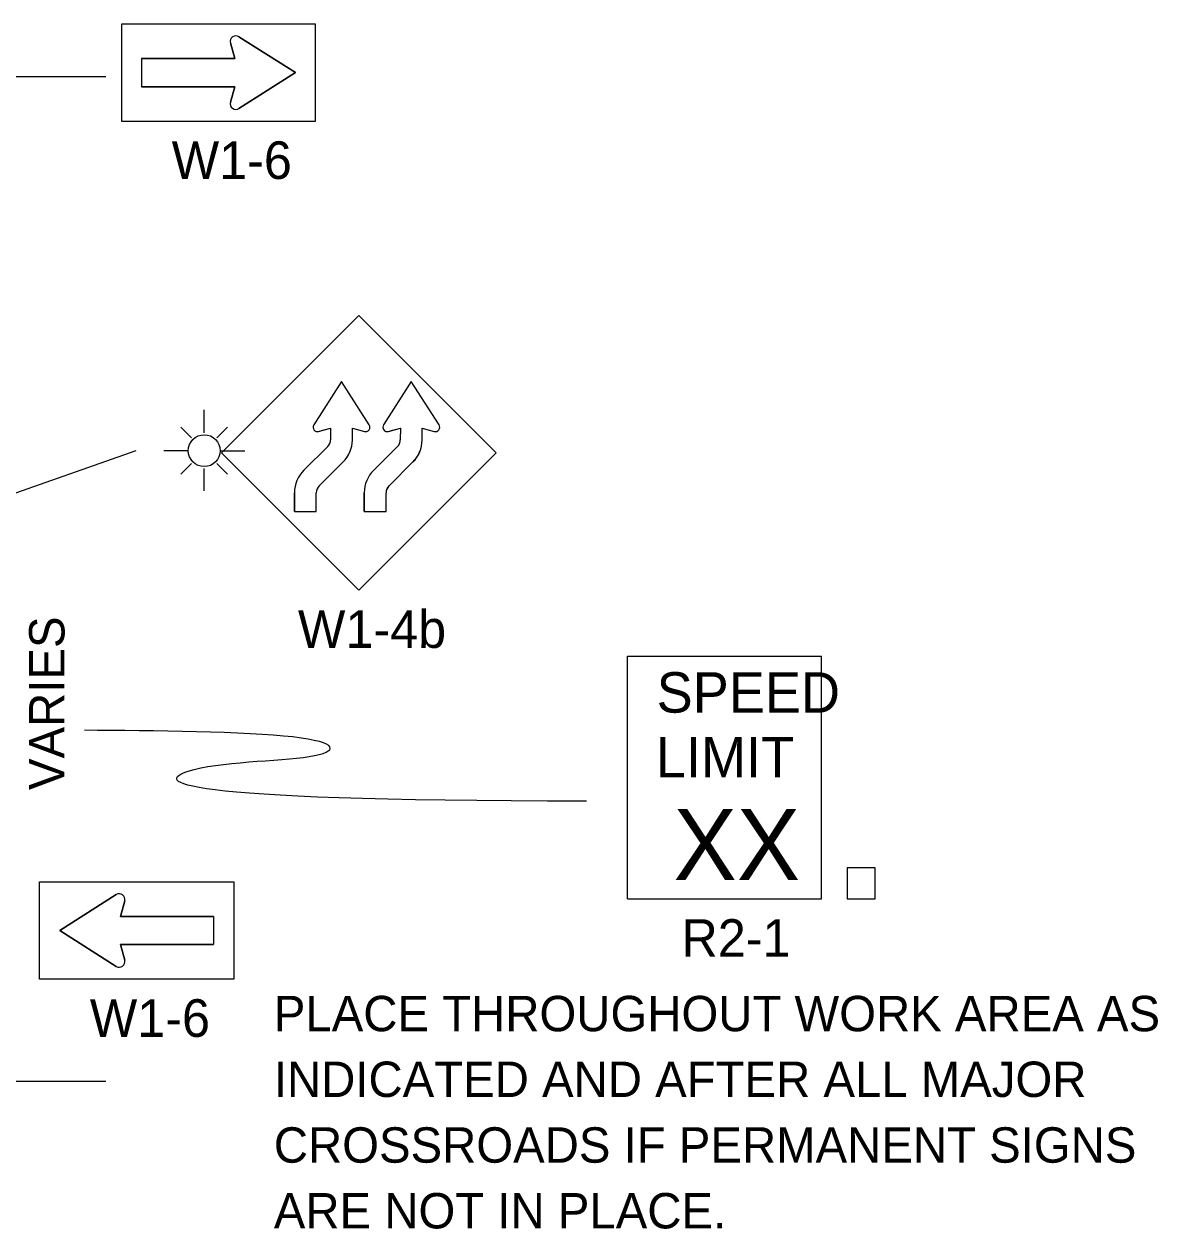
# Model space of a CAD drawing. Extents: x 16765 to 18475, y 6981 to 8262.
# Drawn here: x 17204 to 17428.2, y 7656 to 7894.3 of the extents above; entities that cross this region are included whole.
import ezdxf

# ---------------------------------------------------------------- set-up
doc = ezdxf.new("R2010")
doc.units = 0
doc.layers.add('TRAFFIC_SIGNS_PR', color=7, linetype='Continuous')
doc.layers.add('TYPICAL_TEXT_DIMEN_PR', color=7, linetype='Continuous')

msp = doc.modelspace()

# ---------------------------------------------------------------- linework, layer by layer
at = {"layer": 'TRAFFIC_SIGNS_PR'}
for p, q in [((17245.66, 7887.48), (17244.82, 7890.54)), ((17246.51, 7891.78), (17257.67, 7884.68)), ((17227.26, 7887.48), (17245.66, 7887.48)), ((17227.26, 7887.48), (17227.26, 7881.88)), ((17257.67, 7884.68), (17246.51, 7877.57)), ((17245.66, 7881.88), (17227.26, 7881.88)), ((17244.82, 7878.82), (17245.66, 7881.88)), ((17270.22, 7836.63), (17243.07, 7809.48)), ((17297.37, 7809.48), (17270.22, 7836.63)), ((17239.64, 7813.46), (17239.64, 7817.96)), ((17237.13, 7812.41), (17235.02, 7814.52)), ((17242.15, 7812.41), (17244.26, 7814.52)), ((17236.48, 7809.9), (17231.65, 7809.9)), ((17242.79, 7809.9), (17247.67, 7809.9)), ((17259.35, 7806.01), (17264.07, 7810.73)), ((17264.07, 7810.72), (17259.35, 7806.01)), ((17273.15, 7806.01), (17277.86, 7810.73)), ((17277.86, 7810.72), (17273.15, 7806.01)), ((17237.12, 7807.39), (17235.02, 7805.28)), ((17242.15, 7807.39), (17244.26, 7805.28)), ((17243.07, 7809.48), (17270.22, 7782.32)), ((17262.4, 7802.96), (17267.12, 7807.67)), ((17262.4, 7802.96), (17267.12, 7807.67)), ((17270.22, 7782.32), (17297.37, 7809.48)), ((17276.2, 7802.96), (17280.91, 7807.67)), ((17276.2, 7802.96), (17280.91, 7807.67)), ((17239.64, 7801.93), (17239.64, 7806.35)), ((17257.48, 7797.89), (17257.48, 7801.59)), ((17261.8, 7797.89), (17261.8, 7801.59)), ((17271.28, 7797.89), (17271.28, 7801.59)), ((17275.6, 7797.89), (17275.6, 7801.59)), ((17257.48, 7797.89), (17261.8, 7797.89)), ((17271.28, 7797.89), (17275.6, 7797.89)), ((17323.34, 7769.22), (17361.74, 7769.22)), ((17323.34, 7721.22), (17323.34, 7769.22)), ((17361.74, 7721.22), (17361.74, 7769.22)), ((17222.23, 7722.09), (17211.07, 7714.99)), ((17223.07, 7717.79), (17223.91, 7720.85)), ((17323.34, 7721.22), (17361.74, 7721.22)), ((17241.47, 7717.79), (17223.07, 7717.79)), ((17241.47, 7717.79), (17241.47, 7712.19)), ((17211.07, 7714.99), (17222.23, 7707.88)), ((17223.91, 7709.13), (17223.07, 7712.19)), ((17223.07, 7712.19), (17241.47, 7712.19))]:
    msp.add_line(p, q, dxfattribs=at)
for points in [[(17223.26, 7875.08), (17261.67, 7875.08), (17261.67, 7894.28), (17223.26, 7894.28)], [(17366.76, 7721.22), (17372.35, 7721.22), (17372.35, 7727.39), (17366.76, 7727.39)], [(17245.47, 7705.39), (17207.07, 7705.39), (17207.07, 7724.59), (17245.47, 7724.59)]]:
    msp.add_lwpolyline(points, close=True, dxfattribs=at)
for points in [[(17244.82, 7890.54), (17245.66, 7887.48), (17227.26, 7887.48), (17227.26, 7881.88), (17245.66, 7881.88), (17244.82, 7878.82)], [(17246.51, 7877.57), (17257.67, 7884.68), (17246.51, 7891.78)], [(17272.27, 7815), (17266.79, 7823.61), (17261.31, 7815)], [(17272.27, 7815), (17266.79, 7823.61), (17261.31, 7815)], [(17286.07, 7815), (17280.59, 7823.61), (17275.1, 7815)], [(17286.07, 7815), (17280.59, 7823.61), (17275.1, 7815)], [(17262.27, 7813.7), (17264.63, 7814.35), (17264.63, 7812.06)], [(17262.27, 7813.7), (17263.1, 7813.93), (17264.63, 7814.35), (17264.63, 7812.06)], [(17268.94, 7811.98), (17268.95, 7814.35), (17271.31, 7813.7)], [(17268.94, 7811.98), (17268.95, 7814.35), (17271.31, 7813.7)], [(17276.06, 7813.7), (17278.43, 7814.35), (17278.42, 7812.06)], [(17276.06, 7813.7), (17276.9, 7813.93), (17278.43, 7814.35), (17278.42, 7812.06)], [(17282.74, 7811.98), (17282.74, 7814.35), (17285.11, 7813.7)], [(17282.74, 7811.98), (17282.74, 7814.35), (17285.11, 7813.7)], [(17257.48, 7801.59), (17257.48, 7797.89), (17261.8, 7797.89), (17261.8, 7801.59)], [(17271.28, 7801.59), (17271.28, 7797.89), (17275.6, 7797.89), (17275.6, 7801.59)], [(17222.23, 7707.88), (17211.07, 7714.99), (17222.23, 7722.09)], [(17223.91, 7720.85), (17223.07, 7717.79), (17241.47, 7717.79), (17241.47, 7712.19), (17223.07, 7712.19), (17223.91, 7709.13)]]:
    msp.add_lwpolyline(points, dxfattribs=at)
msp.add_circle((17239.64, 7809.9), 3.15, dxfattribs=at)
for centre, radius, start, end in [((17245.9, 7890.83), 1.12, 57.5304, 195.3269), ((17245.9, 7890.83), 1.12, 57.5304, 195.3269), ((17245.9, 7878.52), 1.12, 164.6731, 302.4696), ((17245.9, 7878.52), 1.12, 164.6731, 302.4696), ((17262.04, 7814.54), 0.864, 147.5204, 285.3986), ((17262.04, 7814.54), 0.866, 147.5288, 285.3852), ((17271.54, 7814.54), 0.866, 254.6828, 32.2708), ((17271.54, 7814.54), 0.866, 254.6799, 32.2804), ((17281.38, 7820.8), 10.8, 212.4569, 212.4665), ((17275.83, 7814.54), 0.864, 147.5204, 285.3986), ((17275.83, 7814.54), 0.866, 147.5288, 285.3852), ((17285.34, 7814.54), 0.866, 254.6828, 32.2708), ((17285.34, 7814.54), 0.866, 254.6799, 32.2804), ((17295.18, 7820.8), 10.8, 212.4569, 212.4665), ((17262.77, 7812.05), 1.85, 314.2123, 0.1238), ((17262.78, 7812.05), 1.85, 314.2125, 0), ((17262.78, 7812.05), 6.17, 314.2125, 359.3819), ((17262.77, 7812.05), 6.17, 314.7687, 359.3755), ((17268.46, 7803.28), 10.8, 74.68, 74.6808), ((17276.57, 7812.05), 1.85, 314.2123, 0.1238), ((17276.57, 7812.05), 1.85, 314.2125, 0), ((17276.57, 7812.05), 6.17, 314.2125, 359.3819), ((17276.57, 7812.05), 6.17, 314.7687, 359.3755), ((17282.25, 7803.28), 10.8, 74.68, 74.6808), ((17263.65, 7801.59), 6.17, 134.2125, 180), ((17263.65, 7801.59), 6.17, 134.2125, 180), ((17263.65, 7801.59), 6.17, 134.2117, 180), ((17277.45, 7801.59), 6.17, 134.2125, 180), ((17277.45, 7801.59), 6.17, 134.2125, 180), ((17277.45, 7801.59), 6.17, 134.2117, 180), ((17263.65, 7801.59), 1.85, 132.372, 180), ((17263.65, 7801.59), 1.85, 134.2125, 180), ((17277.45, 7801.59), 1.85, 132.372, 180), ((17277.45, 7801.59), 1.85, 134.2125, 180), ((17222.83, 7721.14), 1.12, 344.6731, 122.4696), ((17222.83, 7721.14), 1.12, 344.6731, 122.4696), ((17222.83, 7708.83), 1.12, 237.5304, 15.3269), ((17222.83, 7708.83), 1.12, 237.5304, 15.3269)]:
    msp.add_arc(centre, radius, start, end, dxfattribs=at)
at = {"layer": 'TYPICAL_TEXT_DIMEN_PR'}
for p, q in [((17049.47, 7883.9), (17220.2, 7883.9)), ((17226.14, 7809.86), (17195.34, 7799.09)), ((17179.67, 7685.21), (17220.2, 7685.21))]:
    msp.add_line(p, q, dxfattribs=at)
msp.add_open_spline([(17315.23, 7740.58), (17230.45, 7740.58), (17230.45, 7748.45), (17266.41, 7748.45), (17266.41, 7754.1), (17229.39, 7754.54), (17215.98, 7754.59)], degree=3, dxfattribs=at)

# ---------------------------------------------------------------- texts
at = {"layer": 'TRAFFIC_SIGNS_PR'}
for s, height, p in [('W1-6', 7.44, (17233.2, 7863.64)), ('W1-4b', 7.44, (17258.17, 7770.89)), ('SPEED', 8, (17329.11, 7758.08)), ('LIMIT', 8, (17328.95, 7745.28)), ('XX', 14.031, (17332.45, 7724.97)), ('R2-1', 7.44, (17334.02, 7709.78)), ('W1-6', 7.44, (17217.01, 7693.95)), ('PLACE THROUGHOUT WORK AREA AS', 7, (17253.4, 7695.06)), ('INDICATED AND AFTER ALL MAJOR', 7, (17253.4, 7682.06)), ('CROSSROADS IF PERMANENT SIGNS', 7, (17253.4, 7669.06)), ('ARE NOT IN PLACE.', 7, (17253.4, 7656.06))]:
    msp.add_text(s, height=height, dxfattribs=at).set_placement(p)
at = {"layer": 'TYPICAL_TEXT_DIMEN_PR'}
msp.add_text('VARIES', height=7, rotation=90, dxfattribs=at).set_placement((17212, 7742.77))

doc.saveas('drawing.dxf')
